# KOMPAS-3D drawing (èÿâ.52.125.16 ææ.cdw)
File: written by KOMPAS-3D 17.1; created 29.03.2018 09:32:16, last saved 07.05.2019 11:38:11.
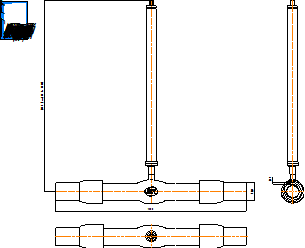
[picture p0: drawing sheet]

Sheet 1: A4, portrait

Title block, sheet 1: name: КШГ.52.125.16 СС; material: Внимание! Данный продукт является объектом авторского права ООО «Торговый Дом АДЛ». / Запрещается изменение, копирование, распространение / (в том числе путем копирования на другие сайты и ресурсы в Интернете) / или любое иное использование информации и объектов без предварительного / согласия правообладателя (ООО «Торговый Дом АДЛ»).; sheets: 1; organisation: ООО "Торговый дом АДЛ"; sheet format: A4; stored path: C:\Users\tra\Desktop\2д чертежи\Шаровые краны БИВАЛ\КШ_Бивал_серия_42_52\KOMPAS 2D\КШГ.52.125.16 СС.cdw

Views: Вид 1, Проекционный вид 2
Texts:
  kka
  adl
  (от 425 до 5000)
Dimensions and other numbers on the sheet: 1500; 140; 15,7; 1:1; 1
